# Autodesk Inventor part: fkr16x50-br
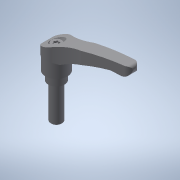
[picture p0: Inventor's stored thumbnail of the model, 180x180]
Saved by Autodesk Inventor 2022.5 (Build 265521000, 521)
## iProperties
Created: 2017-09
Part Number: fkr16x50-br
Material: 一般
Document SubType Name: Modeling
Designer: imaocorp
Density: 1 g/cm^3
Appearance: 既定
Author: imaocorp
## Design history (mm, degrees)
node "fkr16x50-br.x_t1"
node "fkr16x50-br"
node "Base1"
